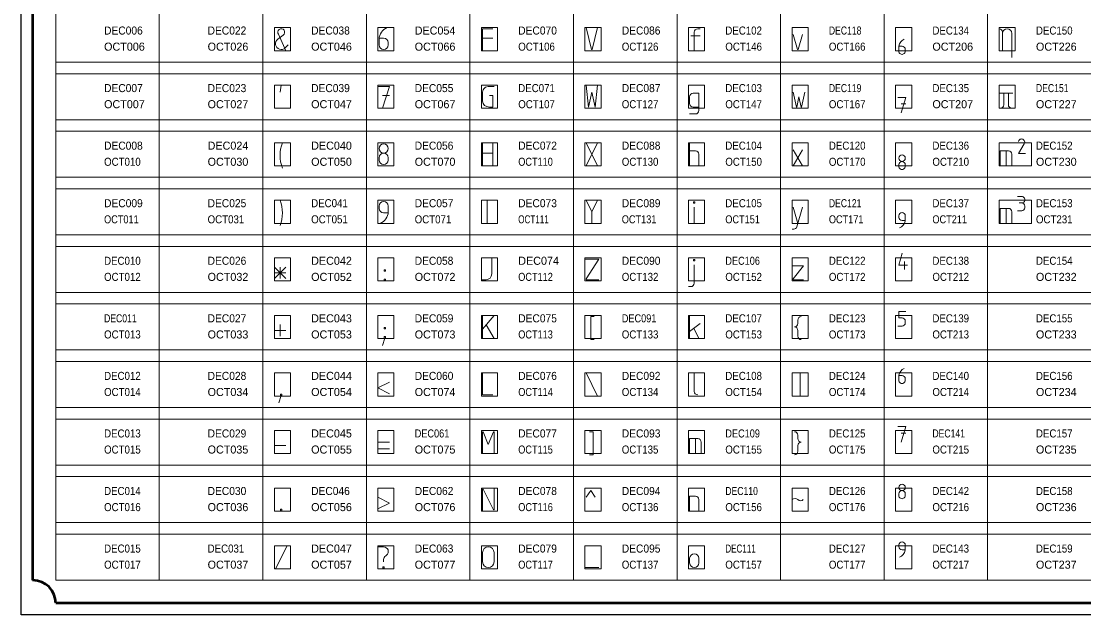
# Model space of a CAD drawing. Extents: x -200 to 7300, y -200 to 4800.
# Drawn here: x -200 to 4418, y -200 to 2378 of the extents above; entities that cross this region are included whole.
import ezdxf

# ---------------------------------------------------------------- set-up
doc = ezdxf.new("R2010")
doc.units = 0
doc.header["$LTSCALE"] = 14
for name, color, linetype, lineweight in [('1', 7, 'Continuous', 13), ('5', 7, 'Continuous', 40), ('6', 7, 'Continuous', 13), ('63', 7, 'Continuous', 13)]:
    doc.layers.add(name, color=color, linetype=linetype, lineweight=lineweight)
doc.layers.add('10', color=7, linetype='Continuous')
doc.layers.add('11', color=7, linetype='Continuous')

msp = doc.modelspace()

# ---------------------------------------------------------------- linework, layer by layer
at = {"layer": '1'}
for p, q in [((939, 2318), (915, 2300)), ((950, 2250), (918, 2321)), ((2710, 2315), (2750, 2315)), ((2725, 2330), (2725, 2250)), ((2750, 2345), (2740, 2345)), ((4065, 2250), (4065, 2330)), ((4105, 2220), (4105, 2325)), ((960, 2275), (947.7, 2262.3)), ((1355, 2305), (1375, 2305)), ((1355, 2300), (1355, 2275)), ((1395, 2285), (1395, 2275)), ((1850, 2305), (1805, 2305)), ((3614, 2270), (3614, 2248)), ((3614, 2269), (3628, 2269)), ((3642, 2255), (3642, 2248)), ((925, 2070), (930, 2100)), ((1855, 2095), (1835, 2095)), ((1370, 2055), (1400, 2055)), ((1805, 2070), (1805, 2030)), ((2705, 2020), (2705, 2050)), ((4050, 2065), (4110, 2065)), ((4070, 2065), (4070, 2015)), ((4090, 2065), (4090, 2015)), ((2745, 2005), (2720, 2005)), ((3624, 2019), (3645, 2019)), ((2730, 1975), (2705, 1975)), ((1805, 1850), (1805, 1750)), ((1850, 1850), (1850, 1750)), ((2255, 1850), (2305, 1750)), ((2305, 1850), (2255, 1750)), ((2705, 1850), (2705, 1750)), ((1805, 1805), (1850, 1805)), ((2705, 1815), (2730, 1815)), ((3155, 1820), (3195, 1750)), ((3195, 1820), (3155, 1750)), ((4080, 1815), (4080, 1750)), ((1355, 1785), (1355, 1775)), ((1395, 1785), (1395, 1775)), ((2745, 1800), (2745, 1750)), ((3614, 1755), (3614, 1748)), ((3642, 1755), (3642, 1748)), ((4105, 1800), (4105, 1750)), ((4148, 1617), (4130, 1617)), ((1355, 1565), (1355, 1575)), ((1395, 1550), (1395, 1575)), ((1825, 1600), (1825, 1500)), ((4148, 1589), (4137, 1589)), ((4162, 1575), (4162, 1568)), ((1395, 1545), (1375, 1545)), ((2280, 1550), (2280, 1500)), ((2725, 1500), (2725, 1570)), ((3155, 1570), (3175, 1500)), ((3195, 1570), (3171, 1485)), ((3614, 1526), (3614, 1533)), ((3642, 1510), (3642, 1533)), ((4080, 1565), (4080, 1500)), ((4105, 1550), (4105, 1500)), ((4148, 1554), (4130, 1554)), ((3642, 1512), (3628, 1512)), ((3157, 1475), (3150, 1475)), ((1845, 1280), (1845, 1350)), ((900, 1260), (950, 1310)), ((900, 1310), (950, 1260)), ((925, 1310), (925, 1260)), ((2725, 1320), (2725, 1240)), ((3638, 1300), (3638, 1335)), ((900, 1285), (950, 1285)), ((1800, 1255), (1820, 1255)), ((2710, 1225), (2700, 1225)), ((1805, 1100), (1805, 1000)), ((1855, 1100), (1805, 1040)), ((2705, 1100), (2705, 1000)), ((2750, 1065), (2705, 1030)), ((3175, 1080), (3175, 1065)), ((3642, 1075), (3642, 1068)), ((900, 1035), (950, 1035)), ((925, 1010), (925, 1060)), ((1821, 1059), (1855, 1000)), ((2745, 1000), (2723, 1044)), ((3175, 1010), (3175, 1035)), ((3610, 1054), (3628, 1054)), ((2305, 750), (2255, 850)), ((2725, 850), (2725, 770)), ((3185, 850), (3185, 750)), ((3614, 840), (3614, 818)), ((3614, 839), (3628, 839)), ((3642, 825), (3642, 818)), ((2730, 565), (2730, 500)), ((3175, 580), (3175, 565)), ((3624, 589), (3645, 589)), ((900, 535), (950, 535)), ((1350, 550), (1400, 550)), ((1350, 520), (1400, 520)), ((2755, 550), (2755, 500)), ((3175, 510), (3175, 535)), ((3614, 325), (3614, 318)), ((3642, 325), (3642, 318)), ((2745, 300), (2745, 250)), ((905, 0), (955, 100)), ((1350, 95), (1375, 95)), ((3614, 96), (3614, 103)), ((3642, 80), (3642, 103)), ((1384, 56), (1387, 59)), ((1805, 70), (1805, 30)), ((1855, 70), (1855, 30)), ((3642, 82), (3628, 82)), ((1375, 30), (1375, 39)), ((2250, 5), (2310, 5)), ((2705, 45), (2705, 25)), ((2745, 45), (2745, 25))]:
    msp.add_line(p, q, dxfattribs=at)
for points in [[(1850, 2345), (1805, 2345), (1805, 2250)], [(2255, 2350), (2279, 2255), (2281, 2255), (2305, 2350)], [(3155, 2320), (3173, 2255), (3177, 2255), (3195, 2320)], [(1350, 2095), (1400, 2095), (1370, 2000)], [(2255, 2100), (2265, 2005), (2266, 2005), (2280, 2070), (2294, 2005), (2295, 2005), (2305, 2100)], [(1835, 2005), (1850, 2005), (1850, 2055), (1835, 2055)], [(2720, 2065), (2745, 2065), (2745, 1990)], [(3155, 2070), (3169, 2005), (3171, 2005), (3180, 2050), (3189, 2005), (3191, 2005), (3205, 2070)], [(3610, 2047), (3645, 2047), (3624, 1980)], [(4055, 1750), (4055, 1815), (4090, 1815)], [(4165, 1804), (4134, 1804), (4159.3, 1844.9)], [(2255, 1600), (2280, 1550), (2305, 1600)], [(4055, 1500), (4055, 1565), (4090, 1565)], [(2250, 1345), (2310, 1345), (2255, 1259), (2255, 1255), (2310, 1255)], [(3652, 1318), (3614, 1318), (3628, 1370)], [(3150, 1315), (3200, 1315), (3155, 1259), (3155, 1255), (3200, 1255)], [(3645, 1117), (3614, 1117), (3614, 1089), (3628, 1089)], [(2290, 1095), (2275, 1095), (2275, 995), (2290, 995)], [(1380, 1002), (1377, 1002), (1377, 1008), (1383, 1008), (1383, 1002), (1380, 1002), (1370, 970)], [(1850, 755), (1805, 755), (1805, 850)], [(1400, 810), (1350, 785), (1400, 760)], [(930, 752), (927, 752), (927, 758), (933, 758), (933, 752), (930, 752), (920, 720)], [(3610, 617), (3645, 617), (3624, 550)], [(1805, 500), (1805, 595), (1807, 595), (1830, 540), (1853, 595), (1855, 595), (1855, 500)], [(2270, 595), (2285, 595), (2285, 495), (2270, 495)], [(2705, 500), (2705, 565), (2740, 565)], [(1805, 250), (1805, 345), (1807, 345), (1853, 255), (1855, 255), (1855, 350)], [(2295, 310), (2275, 340), (2255, 310)], [(1350, 310), (1400, 285), (1350, 260)], [(2705, 250), (2705, 315), (2730, 315)]]:
    msp.add_lwpolyline(points, dxfattribs=at)
for points in [[(2722, 1587), (2728, 1587), (2728, 1593), (2722, 1593)], [(2722, 1337), (2728, 1337), (2728, 1343), (2722, 1343)], [(1377, 1292), (1383, 1292), (1383, 1298), (1377, 1298)], [(1377, 1252), (1383, 1252), (1383, 1258), (1377, 1258)], [(1377, 1042), (1383, 1042), (1383, 1048), (1377, 1048)], [(927, 252), (933, 252), (933, 258), (927, 258)], [(1372, 2), (1378, 2), (1378, 8), (1372, 8)]]:
    msp.add_lwpolyline(points, close=True, dxfattribs=at)
for centre, radius in [((1375, 1825), 20), ((3628, 1783), 14), ((3628, 353), 14)]:
    msp.add_circle(centre, radius, dxfattribs=at)
for centre, radius, start, end in [((930, 2330), 15, 306.8699, 215.2272), ((1411.1, 2297.9), 56.2, 112.1027, 177.9132), ((2740, 2330), 15, 90, 180), ((4050, 2330), 15, 0, 90), ((4085, 2325), 20, 0, 180), ((930, 2280), 25, 126.8699, 315), ((1375, 2275), 20, 180, 360), ((1375, 2285), 20, 0, 90), ((3654.3, 2262.3), 41.1, 113.4429, 169.2375), ((3628, 2255), 14, 0, 90), ((3628, 2248), 14, 179.8538, 0.1462), ((2720, 2050), 15, 90, 180), ((2720, 2020), 15, 180, 270), ((2730, 1990), 15, 270, 0), ((4055, 2015), 15, 270, 0), ((4105, 2015), 15, 180, 270), ((1080, 1795), 155.1, 159.2277, 200.7723), ((4147.5, 1852.5), 14, 327.0948, 165.9638), ((1375, 1785), 20, 0, 180), ((2730, 1800), 15, 0, 90), ((4090, 1800), 15, 0, 90), ((1375, 1775), 20, 180, 360), ((3628, 1755), 14, 0, 180), ((3628, 1748), 14, 179.8538, 0.1462), ((4148, 1603), 14, 265.8439, 90.0653), ((780, 1545), 155.1, 339.2277, 20.7722), ((1375, 1575), 20, 0, 180), ((4148, 1575), 14, 0, 90), ((1375, 1565), 20, 180, 270), ((1338.9, 1552), 56.2, 292.1027, 357.9132), ((3628, 1533), 14, 0, 180), ((3628, 1526), 14, 180, 270), ((4090, 1550), 15, 0, 90), ((4148, 1568), 14, 270, 360), ((3157.1, 1490), 15, 270, 338.5769), ((3603.7, 1516.5), 38.9, 290.0491, 350.3397), ((1820, 1280), 25, 270, 0), ((2710, 1240), 15, 270, 0), ((3160, 1065), 15, 270, 0), ((3190, 1080), 15, 90, 180), ((3628, 1075), 14, 0, 90), ((3628, 1068), 14, 270, 360), ((3160, 1035), 15, 0, 90), ((3190, 1010), 15, 180, 270), ((3654.3, 832.3), 41.1, 113.4429, 169.2375), ((3628, 825), 14, 0, 90), ((3628, 818), 14, 179.8538, 0.1462), ((2740, 770), 15, 180, 270), ((2740, 550), 15, 0, 90), ((3160, 580), 15, 0, 90), ((3190, 565), 15, 180, 270), ((3160, 510), 15, 270, 0), ((3190, 535), 15, 90, 180), ((3628, 325), 14, 0, 180), ((2730, 300), 15, 0, 90), ((3163, 288), 17, 45, 134.9981), ((3187, 312), 17, 225, 314.9981), ((3628, 318), 14, 179.8538, 0.1462), ((1375, 75), 20, 306.8699, 90), ((1830, 70), 25, 0, 180), ((3628, 103), 14, 0, 180), ((3628, 96), 14, 180, 270), ((1395, 39.3), 20, 123.6901, 180), ((2725, 45), 20, 0, 180), ((3603.7, 86.5), 38.9, 290.0491, 350.3397), ((1830, 30), 25, 180, 360), ((2725, 25), 20, 180, 360)]:
    msp.add_arc(centre, radius, start, end, dxfattribs=at)
for centre, major_axis, start_param, end_param in [((1835, 2070), (30, 0), 1.570796, 3.141593), ((1835, 2030), (-30, 0), 6.283185, 7.853981)]:
    msp.add_ellipse(centre, major_axis=major_axis, ratio=0.833333, start_param=start_param, end_param=end_param, dxfattribs=at)
at = {"layer": '5', "lineweight": 53}
for p, q in [((-150, -50), (-150, 4650)), ((7150, -150), (-50, -150))]:
    msp.add_line(p, q, dxfattribs=at)
at = {"layer": '5', "lineweight": 25}
msp.add_lwpolyline([(-200, -200), (-200, 4800), (7300, 4800), (7300, -200)], close=True, dxfattribs=at)
at = {"layer": '5', "lineweight": 53}
msp.add_arc((-150, -150), 100, 0, 90, dxfattribs=at)
at = {"layer": '6'}
for p, q in [((-50, 3950), (-50, -50)), ((400, 3950), (400, -50)), ((850, 3950), (850, -50)), ((1300, 3950), (1300, -50)), ((1750, 3950), (1750, -50)), ((2200, 3950), (2200, -50)), ((2650, 3950), (2650, -50)), ((3100, 3950), (3100, -50)), ((3550, 3950), (3550, -50)), ((4000, 3950), (4000, -50)), ((-50, 2200), (7150, 2200)), ((-50, 2150), (7150, 2150)), ((-50, 1950), (7150, 1950)), ((-50, 1900), (7150, 1900)), ((-50, 1700), (7150, 1700)), ((-50, 1650), (7150, 1650)), ((-50, 1450), (7150, 1450)), ((-50, 1400), (7150, 1400)), ((-50, 1200), (7150, 1200)), ((-50, 1150), (7150, 1150)), ((-50, 950), (7150, 950)), ((-50, 900), (7150, 900)), ((-50, 700), (7150, 700)), ((-50, 650), (7150, 650)), ((-50, 450), (7150, 450)), ((-50, 400), (7150, 400)), ((-50, 200), (7150, 200)), ((-50, 150), (7150, 150)), ((-50, -50), (7150, -50))]:
    msp.add_line(p, q, dxfattribs=at)
at = {"layer": '63'}
for points in [[(900, 2250), (970, 2250), (970, 2350), (900, 2350)], [(1350, 2250), (1420, 2250), (1420, 2350), (1350, 2350)], [(1800, 2250), (1870, 2250), (1870, 2350), (1800, 2350)], [(2250, 2250), (2320, 2250), (2320, 2350), (2250, 2350)], [(2700, 2250), (2770, 2250), (2770, 2350), (2700, 2350)], [(3150, 2250), (3220, 2250), (3220, 2350), (3150, 2350)], [(3600, 2250), (3670, 2250), (3670, 2350), (3600, 2350)], [(4050, 2250), (4120, 2250), (4120, 2350), (4050, 2350)], [(900, 2000), (970, 2000), (970, 2100), (900, 2100)], [(1350, 2000), (1420, 2000), (1420, 2100), (1350, 2100)], [(1800, 2000), (1870, 2000), (1870, 2100), (1800, 2100)], [(2250, 2000), (2320, 2000), (2320, 2100), (2250, 2100)], [(2700, 2000), (2770, 2000), (2770, 2100), (2700, 2100)], [(3150, 2000), (3220, 2000), (3220, 2100), (3150, 2100)], [(3600, 2000), (3670, 2000), (3670, 2100), (3600, 2100)], [(4050, 2000), (4120, 2000), (4120, 2100), (4050, 2100)], [(900, 1750), (970, 1750), (970, 1850), (900, 1850)], [(1350, 1750), (1420, 1750), (1420, 1850), (1350, 1850)], [(1800, 1750), (1870, 1750), (1870, 1850), (1800, 1850)], [(2250, 1750), (2320, 1750), (2320, 1850), (2250, 1850)], [(2700, 1750), (2770, 1750), (2770, 1850), (2700, 1850)], [(3150, 1750), (3220, 1750), (3220, 1850), (3150, 1850)], [(3600, 1750), (3670, 1750), (3670, 1850), (3600, 1850)], [(4050, 1750), (4190, 1750), (4190, 1850), (4050, 1850)], [(900, 1500), (970, 1500), (970, 1600), (900, 1600)], [(1350, 1500), (1420, 1500), (1420, 1600), (1350, 1600)], [(1800, 1500), (1870, 1500), (1870, 1600), (1800, 1600)], [(2250, 1500), (2320, 1500), (2320, 1600), (2250, 1600)], [(2700, 1500), (2770, 1500), (2770, 1600), (2700, 1600)], [(3150, 1500), (3220, 1500), (3220, 1600), (3150, 1600)], [(3600, 1500), (3670, 1500), (3670, 1600), (3600, 1600)], [(4050, 1500), (4190, 1500), (4190, 1600), (4050, 1600)], [(900, 1250), (970, 1250), (970, 1350), (900, 1350)], [(1350, 1250), (1420, 1250), (1420, 1350), (1350, 1350)], [(1800, 1250), (1870, 1250), (1870, 1350), (1800, 1350)], [(2250, 1250), (2320, 1250), (2320, 1350), (2250, 1350)], [(2700, 1250), (2770, 1250), (2770, 1350), (2700, 1350)], [(3150, 1250), (3220, 1250), (3220, 1350), (3150, 1350)], [(3600, 1250), (3670, 1250), (3670, 1350), (3600, 1350)], [(900, 1000), (970, 1000), (970, 1100), (900, 1100)], [(1350, 1000), (1420, 1000), (1420, 1100), (1350, 1100)], [(1800, 1000), (1870, 1000), (1870, 1100), (1800, 1100)], [(2250, 1000), (2320, 1000), (2320, 1100), (2250, 1100)], [(2700, 1000), (2770, 1000), (2770, 1100), (2700, 1100)], [(3150, 1000), (3220, 1000), (3220, 1100), (3150, 1100)], [(3600, 1000), (3670, 1000), (3670, 1100), (3600, 1100)], [(900, 750), (970, 750), (970, 850), (900, 850)], [(1350, 750), (1420, 750), (1420, 850), (1350, 850)], [(1800, 750), (1870, 750), (1870, 850), (1800, 850)], [(2250, 750), (2320, 750), (2320, 850), (2250, 850)], [(2700, 750), (2770, 750), (2770, 850), (2700, 850)], [(3150, 750), (3220, 750), (3220, 850), (3150, 850)], [(3600, 750), (3670, 750), (3670, 850), (3600, 850)], [(900, 500), (970, 500), (970, 600), (900, 600)], [(1350, 500), (1420, 500), (1420, 600), (1350, 600)], [(1800, 500), (1870, 500), (1870, 600), (1800, 600)], [(2250, 500), (2320, 500), (2320, 600), (2250, 600)], [(2700, 500), (2770, 500), (2770, 600), (2700, 600)], [(3150, 500), (3220, 500), (3220, 600), (3150, 600)], [(3600, 500), (3670, 500), (3670, 600), (3600, 600)], [(900, 250), (970, 250), (970, 350), (900, 350)], [(1350, 250), (1420, 250), (1420, 350), (1350, 350)], [(1800, 250), (1870, 250), (1870, 350), (1800, 350)], [(2250, 250), (2320, 250), (2320, 350), (2250, 350)], [(2700, 250), (2770, 250), (2770, 350), (2700, 350)], [(3150, 250), (3220, 250), (3220, 350), (3150, 350)], [(3600, 250), (3670, 250), (3670, 350), (3600, 350)], [(900, 0), (970, 0), (970, 100), (900, 100)], [(1350, 0), (1420, 0), (1420, 100), (1350, 100)], [(1800, 0), (1870, 0), (1870, 100), (1800, 100)], [(2250, 0), (2320, 0), (2320, 100), (2250, 100)], [(2700, 0), (2770, 0), (2770, 100), (2700, 100)], [(3600, 0), (3670, 0), (3670, 100), (3600, 100)]]:
    msp.add_lwpolyline(points, close=True, dxfattribs=at)

# ---------------------------------------------------------------- texts
at = {"layer": '10'}
for s, width, p in [('DEC006', 0.95, (160, 2320)), ('DEC022', 0.95, (610, 2320)), ('DEC038', 0.95, (1060, 2320)), ('DEC070', 0.95, (1960, 2320)), ('DEC086', 0.95, (2410, 2320)), ('DEC102', 0.9, (2860, 2320)), ('DEC118', 0.8, (3310, 2320)), ('DEC134', 0.9, (3760, 2320)), ('DEC150', 0.9, (4210, 2320)), ('DEC007', 0.95, (160, 2070)), ('DEC023', 0.95, (610, 2070)), ('DEC039', 0.95, (1060, 2070)), ('DEC055', 0.95, (1510, 2070)), ('DEC071', 0.9, (1960, 2070)), ('DEC087', 0.95, (2410, 2070)), ('DEC103', 0.9, (2860, 2070)), ('DEC119', 0.8, (3310, 2070)), ('DEC135', 0.9, (3760, 2070)), ('DEC151', 0.8, (4210, 2070)), ('DEC008', 0.95, (160, 1820)), ('DEC056', 0.95, (1510, 1820)), ('DEC072', 0.95, (1960, 1820)), ('DEC088', 0.95, (2410, 1820)), ('DEC104', 0.9, (2860, 1820)), ('DEC120', 0.9, (3310, 1820)), ('DEC136', 0.9, (3760, 1820)), ('DEC152', 0.9, (4210, 1820)), ('DEC009', 0.95, (160, 1570)), ('DEC025', 0.95, (610, 1570)), ('DEC041', 0.9, (1060, 1570)), ('DEC057', 0.95, (1510, 1570)), ('DEC073', 0.95, (1960, 1570)), ('DEC089', 0.95, (2410, 1570)), ('DEC105', 0.9, (2860, 1570)), ('DEC121', 0.8, (3310, 1570)), ('DEC137', 0.9, (3760, 1570)), ('DEC153', 0.9, (4210, 1570)), ('DEC010', 0.9, (160, 1320)), ('DEC026', 0.95, (610, 1320)), ('DEC058', 0.95, (1510, 1320)), ('DEC090', 0.95, (2410, 1320)), ('DEC106', 0.85, (2860, 1320)), ('DEC122', 0.9, (3310, 1320)), ('DEC138', 0.9, (3760, 1320)), ('DEC154', 0.9, (4210, 1320)), ('DEC011', 0.8, (160, 1070)), ('DEC027', 0.95, (610, 1070)), ('DEC059', 0.95, (1510, 1070)), ('DEC075', 0.95, (1960, 1070)), ('DEC091', 0.85, (2410, 1070)), ('DEC107', 0.9, (2860, 1070)), ('DEC123', 0.9, (3310, 1070)), ('DEC139', 0.9, (3760, 1070)), ('DEC155', 0.9, (4210, 1070)), ('DEC012', 0.9, (160, 820)), ('DEC028', 0.95, (610, 820)), ('DEC060', 0.95, (1510, 820)), ('DEC076', 0.95, (1960, 820)), ('DEC092', 0.95, (2410, 820)), ('DEC108', 0.9, (2860, 820)), ('DEC124', 0.9, (3310, 820)), ('DEC140', 0.9, (3760, 820)), ('DEC156', 0.9, (4210, 820)), ('DEC013', 0.9, (160, 570)), ('DEC029', 0.95, (610, 570)), ('DEC061', 0.85, (1510, 570)), ('DEC077', 0.95, (1960, 570)), ('DEC093', 0.95, (2410, 570)), ('DEC109', 0.85, (2860, 570)), ('DEC125', 0.9, (3310, 570)), ('DEC141', 0.8, (3760, 570)), ('DEC157', 0.9, (4210, 570)), ('DEC014', 0.9, (160, 320)), ('DEC030', 0.95, (610, 320)), ('DEC046', 0.95, (1060, 320)), ('DEC062', 0.95, (1510, 320)), ('DEC078', 0.95, (1960, 320)), ('DEC094', 0.95, (2410, 320)), ('DEC110', 0.8, (2860, 320)), ('DEC126', 0.9, (3310, 320)), ('DEC142', 0.9, (3760, 320)), ('DEC158', 0.9, (4210, 320)), ('DEC015', 0.9, (160, 70)), ('DEC031', 0.9, (610, 70)), ('DEC063', 0.95, (1510, 70)), ('DEC079', 0.95, (1960, 70)), ('DEC095', 0.95, (2410, 70)), ('DEC111', 0.75, (2860, 70)), ('DEC127', 0.9, (3310, 70)), ('DEC143', 0.9, (3760, 70)), ('DEC159', 0.9, (4210, 70))]:
    msp.add_text(s, height=35, dxfattribs=dict(at, width=width)).set_placement(p)
for s, p in [('DEC054', (1510, 2320)), ('DEC024', (610, 1820)), ('DEC040', (1060, 1820)), ('DEC042', (1060, 1320)), ('DEC074', (1960, 1320)), ('DEC043', (1060, 1070)), ('DEC044', (1060, 820)), ('DEC045', (1060, 570)), ('DEC047', (1060, 70))]:
    msp.add_text(s, height=35, dxfattribs=at).set_placement(p)
at = {"layer": '11'}
for s, p in [('OCT006', (160, 2250)), ('OCT026', (610, 2250)), ('OCT046', (1060, 2250)), ('OCT066', (1510, 2250)), ('OCT206', (3760, 2250)), ('OCT226', (4210, 2250)), ('OCT007', (160, 2000)), ('OCT027', (610, 2000)), ('OCT047', (1060, 2000)), ('OCT067', (1510, 2000)), ('OCT207', (3760, 2000)), ('OCT227', (4210, 2000)), ('OCT030', (610, 1750)), ('OCT050', (1060, 1750)), ('OCT070', (1510, 1750)), ('OCT230', (4210, 1750)), ('OCT032', (610, 1250)), ('OCT052', (1060, 1250)), ('OCT072', (1510, 1250)), ('OCT232', (4210, 1250)), ('OCT033', (610, 1000)), ('OCT053', (1060, 1000)), ('OCT073', (1510, 1000)), ('OCT233', (4210, 1000)), ('OCT034', (610, 750)), ('OCT054', (1060, 750)), ('OCT074', (1510, 750)), ('OCT234', (4210, 750)), ('OCT035', (610, 500)), ('OCT055', (1060, 500)), ('OCT075', (1510, 500)), ('OCT235', (4210, 500)), ('OCT036', (610, 250)), ('OCT056', (1060, 250)), ('OCT076', (1510, 250)), ('OCT236', (4210, 250)), ('OCT037', (610, 0)), ('OCT057', (1060, 0)), ('OCT077', (1510, 0)), ('OCT237', (4210, 0))]:
    msp.add_text(s, height=35, dxfattribs=at).set_placement(p)
for s, width, p in [('OCT106', 0.9, (1960, 2250)), ('OCT126', 0.9, (2410, 2250)), ('OCT146', 0.9, (2860, 2250)), ('OCT166', 0.9, (3310, 2250)), ('OCT107', 0.9, (1960, 2000)), ('OCT127', 0.9, (2410, 2000)), ('OCT147', 0.9, (2860, 2000)), ('OCT167', 0.9, (3310, 2000)), ('OCT010', 0.9, (160, 1750)), ('OCT110', 0.85, (1960, 1750)), ('OCT130', 0.9, (2410, 1750)), ('OCT150', 0.9, (2860, 1750)), ('OCT170', 0.9, (3310, 1750)), ('OCT210', 0.9, (3760, 1750)), ('OCT011', 0.85, (160, 1500)), ('OCT031', 0.9, (610, 1500)), ('OCT051', 0.9, (1060, 1500)), ('OCT071', 0.9, (1510, 1500)), ('OCT111', 0.75, (1960, 1500)), ('OCT131', 0.85, (2410, 1500)), ('OCT151', 0.85, (2860, 1500)), ('OCT171', 0.85, (3310, 1500)), ('OCT211', 0.85, (3760, 1500)), ('OCT231', 0.9, (4210, 1500)), ('OCT012', 0.9, (160, 1250)), ('OCT112', 0.85, (1960, 1250)), ('OCT132', 0.9, (2410, 1250)), ('OCT152', 0.9, (2860, 1250)), ('OCT172', 0.9, (3310, 1250)), ('OCT212', 0.9, (3760, 1250)), ('OCT013', 0.9, (160, 1000)), ('OCT113', 0.85, (1960, 1000)), ('OCT133', 0.9, (2410, 1000)), ('OCT153', 0.9, (2860, 1000)), ('OCT173', 0.9, (3310, 1000)), ('OCT213', 0.9, (3760, 1000)), ('OCT014', 0.9, (160, 750)), ('OCT114', 0.85, (1960, 750)), ('OCT134', 0.9, (2410, 750)), ('OCT154', 0.9, (2860, 750)), ('OCT174', 0.9, (3310, 750)), ('OCT214', 0.9, (3760, 750)), ('OCT015', 0.9, (160, 500)), ('OCT115', 0.85, (1960, 500)), ('OCT135', 0.9, (2410, 500)), ('OCT155', 0.9, (2860, 500)), ('OCT175', 0.9, (3310, 500)), ('OCT215', 0.9, (3760, 500)), ('OCT016', 0.9, (160, 250)), ('OCT116', 0.85, (1960, 250)), ('OCT136', 0.9, (2410, 250)), ('OCT156', 0.9, (2860, 250)), ('OCT176', 0.9, (3310, 250)), ('OCT216', 0.9, (3760, 250)), ('OCT017', 0.9, (160, 0)), ('OCT117', 0.85, (1960, 0)), ('OCT137', 0.9, (2410, 0)), ('OCT157', 0.9, (2860, 0)), ('OCT177', 0.9, (3310, 0)), ('OCT217', 0.9, (3760, 0))]:
    msp.add_text(s, height=35, dxfattribs=dict(at, width=width)).set_placement(p)

doc.saveas('drawing.dxf')
